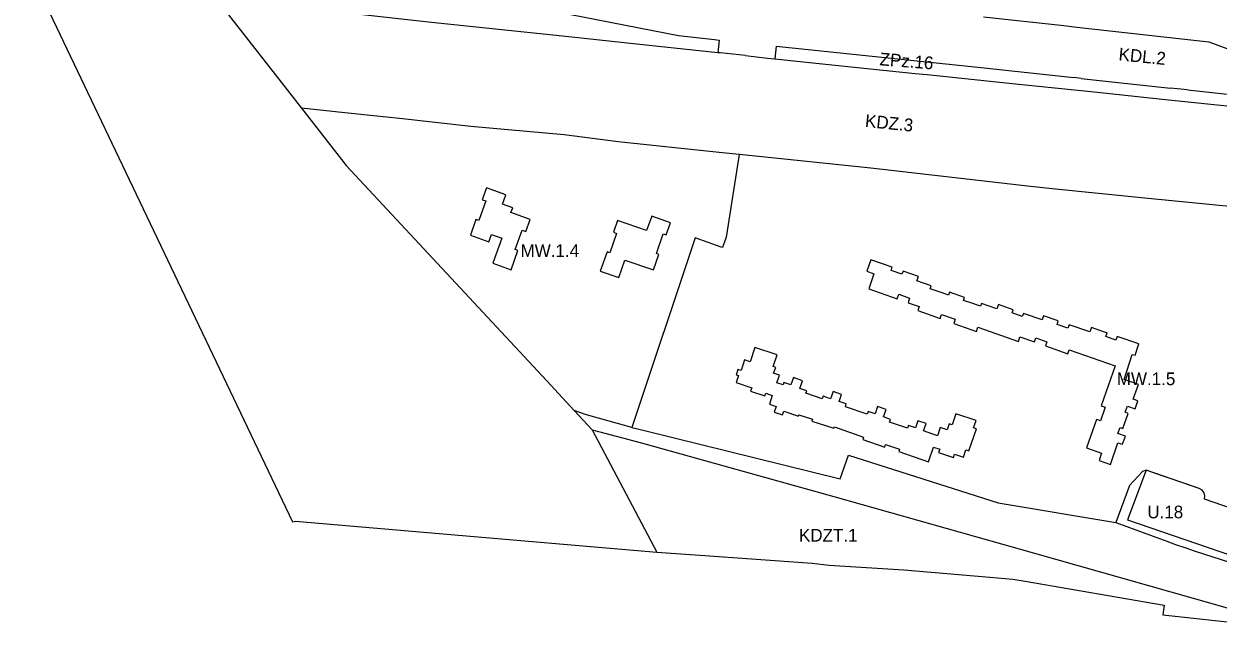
# Model space of a CAD drawing. Extents: x 7428239 to 7429836, y 5549133 to 5550853.
# Drawn here: x 7428542.7 to 7429012.7, y 5549168.2 to 5549408.8 of the extents above; entities that cross this region are included whole.
import ezdxf

# ---------------------------------------------------------------- set-up
doc = ezdxf.new("R2010")
doc.units = 0
for name, color, linetype in [('LIN_linie rozgraniczające', 7, 'Continuous'), ('LIN_nieprzekraczalna linia zabudowy', 7, 'Continuous'), ('LIN_obowiązująca linia zabudowy', 7, 'Continuous'), ('TXT_Oznaczenia Przeznaczenia', 7, 'Continuous')]:
    doc.layers.add(name, color=color, linetype=linetype)

msp = doc.modelspace()

# ---------------------------------------------------------------- linework, layer by layer
at = {"layer": 'LIN_linie rozgraniczające'}
for p, q in [((7428542.7, 5549434.61), (7428648.42, 5549212.88)), ((7428816.35, 5549402.47), (7428815.8, 5549397.49)), ((7428838.82, 5549400.1), (7428838.26, 5549395.07)), ((7428838.82, 5549400.1), (7428918.1, 5549391.83)), ((7428958.86, 5549387.31), (7428955.89, 5549387.71)), ((7428958.86, 5549387.31), (7428993.95, 5549383.57)), ((7429000.6, 5549382.84), (7428993.95, 5549383.57)), ((7428648.42, 5549212.88), (7428649.57, 5549213.12)), ((7428852.92, 5549196.57), (7428859.68, 5549195.71)), ((7428859.68, 5549195.71), (7428889.03, 5549193.93)), ((7428889.03, 5549193.93), (7428922.9, 5549191.01)), ((7428922.9, 5549191.01), (7428931.94, 5549190.23)), ((7428931.94, 5549190.23), (7428936.7, 5549189.41)), ((7428936.7, 5549189.41), (7428991.52, 5549180.03)), ((7428991.52, 5549180.03), (7428990.9, 5549176.27)), ((7428990.9, 5549176.27), (7429018.7, 5549173.26))]:
    msp.add_line(p, q, dxfattribs=at)
for points in [[(7428618.49, 5549418.54), (7428651.96, 5549375.64)], [(7428755.81, 5549412.91), (7428758.02, 5549412.48), (7428800.35, 5549404.28), (7428814.55, 5549402.65)], [(7428826.76, 5549396.33), (7428816.76, 5549397.43), (7428815.8, 5549397.49), (7428778.99, 5549401.37), (7428757.12, 5549403.69), (7428724.48, 5549407.19), (7428703.17, 5549409.39), (7428675.97, 5549412.33)], [(7428920.34, 5549411.54), (7428951.94, 5549408.14), (7428957.12, 5549407.58), (7429009.09, 5549401.82), (7429027.13, 5549395.01), (7429041.39, 5549393.62), (7429059.28, 5549391.87), (7429065.83, 5549391.23), (7429085.85, 5549389.28), (7429090.38, 5549392.28), (7429092.31, 5549393.56), (7429092.68, 5549393.81)], [(7428814.55, 5549402.65), (7428816.35, 5549402.46)], [(7428826.76, 5549396.33), (7428835.33, 5549395.39)], [(7428835.33, 5549395.39), (7428838.26, 5549395.07), (7428849.42, 5549393.84), (7428893.5, 5549389.32), (7428898.14, 5549388.85), (7428931.67, 5549385.42), (7428965.2, 5549382), (7428990.69, 5549379.21), (7429017.46, 5549376.5), (7429079.21, 5549369.9), (7429126.95, 5549364.42), (7429127.1, 5549364.41)], [(7428918.1, 5549391.83), (7428955.89, 5549387.71)], [(7429000.6, 5549382.84), (7429127.79, 5549369.13), (7429127.1, 5549364.41)], [(7428680.26, 5549372.69), (7428668.99, 5549373.86), (7428651.96, 5549375.64)], [(7428651.96, 5549375.64), (7428669.55, 5549353.09), (7428748.45, 5549268.3), (7428759.33, 5549256.6), (7428766.32, 5549249.09), (7428791.76, 5549200.94)], [(7428938.83, 5549344.78), (7428876.06, 5549352.01), (7428830.64, 5549356.76), (7428824.18, 5549357.43), (7428816.29, 5549358.26), (7428776.61, 5549362.45), (7428755.31, 5549365.13), (7428718.64, 5549368.39), (7428690.49, 5549371.54), (7428680.26, 5549372.69)], [(7428824.18, 5549357.43), (7428819.13, 5549324.89), (7428817.7, 5549320.8), (7428817.17, 5549320.98), (7428806.87, 5549324.57), (7428782.01, 5549249.94), (7428764.08, 5549254.88), (7428759.33, 5549256.6)], [(7429123.78, 5549325.92), (7429105.9, 5549327.83), (7429084.89, 5549330.08), (7429043.79, 5549334.28), (7428985.21, 5549340.08), (7428947.39, 5549343.91), (7428938.83, 5549344.78)], [(7428766.32, 5549249.09), (7428785.3, 5549244.05), (7428861.41, 5549222.78), (7428928.37, 5549203.85), (7428940.4, 5549200.46), (7429011.61, 5549180.33), (7429033.89, 5549173.88), (7429050.53, 5549168.23)], [(7428782.01, 5549249.94), (7428786.93, 5549248.73), (7428863.9, 5549229.77), (7428867.22, 5549239.06), (7428926.12, 5549220.34), (7428972.45, 5549212.5), (7428992.52, 5549205.27), (7428995.96, 5549203.93), (7428999.99, 5549202.63), (7429003.28, 5549201.44), (7429028.18, 5549193.43), (7429037.02, 5549217.7)], [(7429035.03, 5549212.23), (7429024.75, 5549215.75), (7429015, 5549219.08), (7429007.34, 5549221.7), (7429007.51, 5549223), (7429007.17, 5549224.29), (7429006.37, 5549225.34), (7429005.22, 5549226), (7429000.77, 5549227.53), (7428991.03, 5549230.85), (7428984.39, 5549233.12), (7428982.97, 5549232.69), (7428977.88, 5549227.09), (7428972.45, 5549212.5)], [(7428649.57, 5549213.12), (7428706.12, 5549208.28), (7428791.76, 5549200.94)], [(7428791.76, 5549200.94), (7428812.49, 5549199.46), (7428852.92, 5549196.57)]]:
    msp.add_lwpolyline(points, dxfattribs=at)
at = {"layer": 'LIN_nieprzekraczalna linia zabudowy'}
msp.add_lwpolyline([(7429032.79, 5549213), (7429007.34, 5549221.7), (7429007.51, 5549223), (7429007.17, 5549224.29), (7429006.37, 5549225.34), (7429005.22, 5549226), (7428984.39, 5549233.12), (7428977, 5549213.56), (7429027.12, 5549196.44), (7429032.79, 5549213)], dxfattribs=at)
at = {"layer": 'LIN_obowiązująca linia zabudowy'}
for points in [[(7428734.39, 5549334.58), (7428735.07, 5549336.46), (7428731.07, 5549337.9), (7428732.36, 5549341.49), (7428724.74, 5549344.23), (7428723.08, 5549339.62), (7428724.47, 5549339.12), (7428721.69, 5549331.4), (7428720.62, 5549331.78), (7428718.43, 5549325.69), (7428725.72, 5549323.08), (7428726.76, 5549325.97), (7428730.83, 5549324.51), (7428727.27, 5549314.59), (7428734.41, 5549312.02), (7428737.15, 5549319.64), (7428736.04, 5549320.04), (7428738.76, 5549327.61), (7428740.19, 5549327.1), (7428741.91, 5549331.88)], [(7428776.31, 5549331.48), (7428774.69, 5549326.8), (7428775.93, 5549326.37), (7428773.27, 5549318.72), (7428772.27, 5549319.08), (7428769.51, 5549311.49), (7428776.84, 5549308.95), (7428779.23, 5549315.87), (7428790.49, 5549311.98), (7428792.6, 5549318.08), (7428791.64, 5549318.41), (7428794.33, 5549326.19), (7428795.48, 5549325.79), (7428797.14, 5549330.58), (7428789.78, 5549333.19), (7428787.7, 5549327.54)], [(7428970.28, 5549235.42), (7428973.28, 5549243.96), (7428975.07, 5549243.33), (7428976.22, 5549246.58), (7428973.29, 5549247.62), (7428974.12, 5549249.97), (7428975.26, 5549249.58), (7428977.35, 5549255.52), (7428976.17, 5549255.93), (7428977.03, 5549258.39), (7428980.05, 5549257.32), (7428981.14, 5549260.43), (7428979.3, 5549261.08), (7428981.33, 5549266.84), (7428975.68, 5549268.83), (7428978.85, 5549278.74), (7428979.99, 5549278.37), (7428981.44, 5549282.89), (7428972.94, 5549285.82), (7428972.44, 5549284.38), (7428968.5, 5549285.75), (7428968.99, 5549287.18), (7428968.4, 5549287.39), (7428962.82, 5549289.31), (7428962.23, 5549287.61), (7428954.1, 5549290.41), (7428953.56, 5549289.06), (7428949.31, 5549290.51), (7428949.78, 5549291.9), (7428944.04, 5549293.94), (7428943.42, 5549292.3), (7428936.06, 5549294.89), (7428935.63, 5549293.66), (7428931.61, 5549295.08), (7428932.04, 5549296.3), (7428926.2, 5549298.36), (7428925.61, 5549296.65), (7428919.52, 5549298.74), (7428919.14, 5549297.66), (7428914.93, 5549299.14), (7428912.52, 5549299.98), (7428912.92, 5549301.12), (7428907.02, 5549303.19), (7428906.63, 5549302.05), (7428904.13, 5549302.93), (7428899.41, 5549304.59), (7428899.81, 5549305.73), (7428894.15, 5549307.72), (7428894.75, 5549309.42), (7428888.72, 5549311.54), (7428888.28, 5549310.29), (7428884.04, 5549311.78), (7428884.48, 5549313.03), (7428876.07, 5549315.99), (7428874.47, 5549311.46), (7428877.26, 5549310.49), (7428875.17, 5549304.54), (7428886.4, 5549300.59), (7428887.03, 5549302.38), (7428891.3, 5549300.83), (7428890.68, 5549299.09), (7428895.03, 5549297.56), (7428894.46, 5549295.96), (7428903.33, 5549292.83), (7428903.89, 5549294.44), (7428909.27, 5549292.54), (7428908.71, 5549290.94), (7428917.55, 5549287.72), (7428918.14, 5549289.43), (7428934.08, 5549283.82), (7428934.7, 5549285.62), (7428940.37, 5549283.63), (7428940.95, 5549285.27), (7428945.27, 5549283.7), (7428944.71, 5549282.09), (7428953.58, 5549278.98), (7428954.14, 5549280.58), (7428972.2, 5549274.23), (7428966.67, 5549258.48), (7428968.22, 5549257.93), (7428966.4, 5549252.58), (7428964.79, 5549253.15), (7428960.85, 5549241.92), (7428966.85, 5549239.82), (7428965.84, 5549236.99)], [(7428839.16, 5549278.55), (7428830.4, 5549281.42), (7428828.57, 5549275.84), (7428826.32, 5549276.57), (7428824.96, 5549272.42), (7428823.67, 5549272.84), (7428822.97, 5549270.72), (7428823.92, 5549270.41), (7428823.01, 5549267.64), (7428829.14, 5549265.63), (7428828.71, 5549264.31), (7428834.37, 5549262.45), (7428834.68, 5549263.41), (7428837.22, 5549262.57), (7428836.1, 5549259.15), (7428838.76, 5549258.27), (7428838.01, 5549256), (7428841.26, 5549254.93), (7428841.73, 5549256.36), (7428847.5, 5549254.46), (7428847.65, 5549254.95), (7428853.04, 5549253.18), (7428852.81, 5549252.48), (7428861.47, 5549249.64), (7428861.66, 5549250.2), (7428873.2, 5549246.16), (7428872.88, 5549245.24), (7428881.48, 5549242.22), (7428881.85, 5549243.29), (7428887.34, 5549241.37), (7428887.02, 5549240.46), (7428898.67, 5549236.46), (7428900.66, 5549242.27), (7428903.13, 5549241.42), (7428902.68, 5549240.12), (7428908.5, 5549238.12), (7428908.95, 5549239.44), (7428912.47, 5549238.23), (7428913.47, 5549241.14), (7428914.6, 5549240.75), (7428917.59, 5549249.47), (7428916.49, 5549249.85), (7428917.46, 5549252.67), (7428909.51, 5549255.4), (7428908, 5549251), (7428906.83, 5549251.4), (7428906.01, 5549249.03), (7428903.34, 5549249.94), (7428902.24, 5549246.73), (7428896.81, 5549248.6), (7428897.81, 5549251.5), (7428894.55, 5549252.62), (7428893.58, 5549249.78), (7428890.85, 5549250.72), (7428890.48, 5549249.64), (7428883.42, 5549252.06), (7428883.8, 5549253.16), (7428881.06, 5549254.1), (7428882.06, 5549257.01), (7428878.7, 5549258.16), (7428877.72, 5549255.3), (7428874.99, 5549256.23), (7428874.63, 5549255.19), (7428866, 5549258.15), (7428866.37, 5549259.23), (7428863.54, 5549260.21), (7428864.5, 5549263.01), (7428861.2, 5549264.14), (7428860.19, 5549261.21), (7428857.24, 5549262.23), (7428856.9, 5549261.24), (7428850.49, 5549263.44), (7428850.83, 5549264.43), (7428848.14, 5549265.35), (7428849.17, 5549268.34), (7428845.57, 5549269.58), (7428844.6, 5549266.76), (7428841.84, 5549267.7), (7428841.52, 5549266.74), (7428839.09, 5549267.58), (7428840.09, 5549270.49), (7428837.78, 5549271.28), (7428838.58, 5549273.62), (7428837.59, 5549273.96)]]:
    msp.add_lwpolyline(points, close=True, dxfattribs=at)

# ---------------------------------------------------------------- texts
at = {"layer": 'TXT_Oznaczenia Przeznaczenia'}
for s, rotation, p in [('KDL.2', 354.2329, (7428973.36, 5549394.5)), ('ZPz.16', 355.5081, (7428879.33, 5549392.55)), ('KDZ.3', 354.2329, (7428873.57, 5549368.29))]:
    msp.add_text(s, height=5, rotation=rotation, dxfattribs=at).set_placement(p)
for s, p in [('MW.1.4', (7428738.17, 5549317.06)), ('MW.1.5', (7428972.82, 5549266.62)), ('U.18', (7428984.83, 5549214.2)), ('KDZT.1', (7428847.76, 5549205.05))]:
    msp.add_text(s, height=5, dxfattribs=at).set_placement(p)

doc.saveas('drawing.dxf')
